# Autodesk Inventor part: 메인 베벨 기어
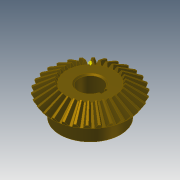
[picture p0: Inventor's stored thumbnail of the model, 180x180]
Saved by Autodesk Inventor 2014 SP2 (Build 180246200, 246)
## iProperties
Created: 2014-10
Part Number: 메인 베벨 기어
Material: Steel, Mild
Document SubType Name: Modeling
Designer: KYOUNG IL JANG
Categories: <?xml version="1.0" encoding="UTF-16"?> <MemberInstance><Categories><FamilyTemplate><FamilyTemplateParameter ValueType="xs:double" Id="1" ObjectReferenceKey="da
Mass: 269.583 g
Surface Area: 108.837 cm^2
Volume: 34.2981 cm^3
Density: 7.86 g/cm^3
Appearance: 얼룩무늬
CustomPartVersion: 1
Company: 한국ATC센터
Author: KYOUNG IL JANG
Revision Number: 1
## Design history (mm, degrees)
node "맨 위 점"
node "메쉬 평면2"
sketch "톱니 본체 스케치"
  geometry: L1 (0, 0)-(28.669, -21.997); L2 (28.669, -21.997)-(31.109, -18.336); L3 (31.109, -18.336)-(0, 0); L4 (30, -20)-(0, 0); L5 (17.219, -13.212)-(18.685, -11.013); L6 (28.669, -21.997)-(17.219, -13.212); L7 (31.109, -18.336)-(18.685, -11.013); L8 (0, -39.387)-(0, 6.564) reference; L9 (0, -20)-(31.109, -20)
  constraints: 16 end point, 4 point on line, 3 perpendicular, 2 collinear, 1 horizontal alignment, 1 vertical alignment
  dimensions: "d0" = 60 diameter of L4.start L8 (= da_de); "d1" = 57.33744 diameter of L1.end L8 (= da_dfe); "d2" = 62.2188 diameter of L2.end L8 (= da_dae); "d3" = 14.4 distance between parallel lines of L2 L5 (= da_b); "d4" = 18.3359 vertical distance of L2.end L1.start (= da_ve)
revolve "톱니 본체" sketch "톱니 본체 스케치" stored, may be unused: angle "d5" = 90 deg
node "시작점"
node "톱니 평면"
sketch "시작 스케치"
  geometry: L1 (0, -23.505)-(0, 10.645) reference; L2 (-0.709, -2.928)-(0.709, -2.928); A1 r 19.188 centre (-19.457, -7.014) between (-0.709, -2.928) and (-3.232, 3.229); A2 r 19.188 centre (19.457, -7.014) between (3.232, 3.229) and (0.709, -2.928); A3 r 57.403 centre (0, -54.083) between (3.232, 3.229) and (-3.232, 3.229); 1 further point
  constraints: 6 point on circle, 3 centre point, 3 symmetric about line, 2 end point, 1 coincident, 1 perpendicular, 1 other
  dimensions: "d7" = 19.18795 radius of A1 (= fd_rr); "d8" = 19.45712 horizontal distance of point (0, -54.083) A1.centre (= fd_x); "d9" = 47.06905 vertical distance of point (0, -54.083) A1.centre (= fd_y); "d57" = 57.40327 radius of A3 (= 0.5 x fd_dva + 0.3 x da_he); "d58" = 51.15527 distance from line of A3.centre L2 (= 0.5 x fd_dva - 1.12 x da_he)
node "끝점"
  node "끝 평면"
sketch "3D 스케치 오른쪽"
  node "Helical Curve Right" dims "d65" = 229.90621 (computed from da_dm, da_delta, da_beta), "d66" = 31.5, "d67" = 60 (= da_de), "d68" = -9.82794 (= -da_delta), "d69" = 8.10972 (computed from fd_loft, da_delta)
node "끝 평면 오른쪽"
sketch "끝 스케치 오른쪽"
  geometry: L1 (0, -41.54)-(0, 13.178) reference; L2 (-0.422, -1.69)-(0.422, -1.69); A1 r 11.427 centre (-11.587, -4.123) between (-0.422, -1.69) and (-1.925, 1.977); A2 r 11.427 centre (11.587, -4.123) between (1.925, 1.977) and (0.422, -1.69); A3 r 34.184 centre (0, -32.153) between (1.925, 1.977) and (-1.925, 1.977); 1 further point
  constraints: 6 point on circle, 3 centre point, 3 symmetric about line, 2 end point, 1 coincident, 1 perpendicular, 1 other
  dimensions: "d70" = 11.58699 horizontal distance of A3.centre A1.centre (computed from fd_x, fd_ratio); "d71" = 28.03028 vertical distance of point (0, -32.153) A1.centre (computed from fd_y, fd_ratio); "d72" = 11.4267 radius of A1 (computed from fd_rr, fd_ratio); "d73" = 30.46369 distance from line of point (0, -32.153) L2 (computed from d58, fd_ratio); "d74" = 34.18446 radius of A3 (computed from d57, fd_ratio)
feature "로프트 오른쪽" sketch "끝 스케치 오른쪽" dims "d75" = 0, "d77" = 0, "d79" = 0, "d80" = 90 deg, "d85" = 20, "d92" = 90 deg, "d93" = 90 deg, "da_teethtype" = 0 [user parameter]
sketch "3D 스케치 왼쪽"
  node "Helical Curve Left" dims "d26" = 229.90621 (computed from da_dm, da_delta, da_beta), "d27" = 8.10972 (computed from fd_loft, da_delta), "d28" = 60 (= da_de), "d29" = -9.82794 (= -da_delta)
node "끝 평면 왼쪽"
sketch "끝 스케치 왼쪽" dims "d56" = 10.3728 (derived)
  geometry: L1 (0, -43.753)-(0, 15.405) reference; L2 (-0.422, -1.678)-(0.422, -1.678); A1 r 11.427 centre (-11.587, -4.111) between (-0.422, -1.678) and (-1.925, 1.988); A2 r 11.427 centre (11.587, -4.111) between (1.925, 1.988) and (0.422, -1.678); A3 r 34.184 centre (0, -32.142) between (1.925, 1.988) and (-1.925, 1.988); 2 further points; 1 other entity
  constraints: 6 point on circle, 3 centre point, 3 symmetric about line, 2 end point, 1 coincident, 2 other
  dimensions: "d30" = 11.4267 radius of A1 (computed from fd_rr, fd_ratio); "d31" = 11.58699 horizontal distance of point (0, -32.142) A1.centre (computed from fd_x, fd_ratio); "d32" = 28.03028 vertical distance of A1.centre point (0, -32.142) (computed from fd_y, fd_ratio); "d61" = 34.18446 radius of A3 (computed from d57, fd_ratio); "d62" = 30.46369 distance from line of point (0, -32.142) L2 (computed from d58, fd_ratio)
feature "로프트 왼쪽" sketch "끝 스케치 왼쪽" dims "d35" = 0, "d37" = 0, "d39" = 0, "d40" = 90 deg, "d84" = 10, "d90" = 90 deg, "d91" = 90 deg, "da_teethtype" = 0 [user parameter]
sketch "본체 스케치"
  geometry: L1 (0, -35.038)-(0, -19.531) reference; L2 (28.669, -21.997)-(17.219, -13.212) reference; L3 (17.219, -13.212)-(0, -13.212); L4 (28.669, -21.997)-(0, -21.997)
  constraints: 4 end point, 2 perpendicular, 2 point on line
revolve "본체 고정" sketch "본체 스케치" stored, may be unused: angle "d46" = 90 deg
feature "피치 지름" dims angle "d47" = 90 deg
sketch "스케치8"
  geometry: C1 r 22.5 at (0, 0); 1 further point
  constraints: 1 centre point, 1 coincident
  dimensions: "d94" = 45 diameter of C1
extrude "돌출1" join sketch "스케치8" distance "d95" = 13; taper "d96" = 0 deg
sketch "스케치9"
  geometry: 1 further point
hole "구멍1" sketch "스케치9" at (0, 0) diameter "d97" = 17; stored, may be unused: countersink angle "d101" = 90 deg, drill point angle "d103" = 118 deg; dims "d98" = 6, "d99" = 4, "d100" = 2, "d102" = 8
sketch "스케치10"
  geometry: L1 (8.124, 2.5)-(10.8, 2.5); L2 (10.8, 2.5)-(10.8, -2.5); L3 (10.8, -2.5)-(8.124, -2.5); A1 r 8.5 centre (0, 0) between (8.124, 2.5) and (8.124, -2.5) reference; 1 further point
  constraints: 6 end point, 2 parallel, 2 point on circle, 1 horizontal, 1 perpendicular
  dimensions: "d104" = 5 distance of L1.end L2.end; "d112" = 19.3 dimension on A1 L2
extrude "돌출2" cut sketch "스케치10" stored distance "d106" = 10; taper "d107" = 0 deg
chamfer "모따기1" distance "d108" = 1; stored, may be unused: second distance "d109" = 2, angle "d110" = 45 deg
fillet "모깎기1" dims "d111" = 2
body "Solid1"
feature "로프트" dims "d17" = 0, "d18" = 90 deg, "d19" = 0, "d20" = 90 deg, "d89" = 0, "da_teethtype" = 0 [user parameter]
pattern_circular "원형 패턴" dims angle "d22" = 360 deg, "d88" = 0, "da_teethtype" = 0 [user parameter]
pattern_circular "원형 패턴 오른쪽" dims angle "d82" = 360 deg, "da_teethtype" = 0 [user parameter]
pattern_circular "원형 패턴 왼쪽" dims angle "d42" = 360 deg, "da_teethtype" = 0 [user parameter]
sketch "끝 스케치"
  geometry: L1 (0, -15.359)-(0, 6.983) reference; L2 (-0.422, -1.69)-(0.422, -1.69); A1 r 11.427 centre (-11.587, -4.123) between (-0.422, -1.69) and (-1.925, 1.977); A2 r 11.427 centre (11.587, -4.123) between (1.925, 1.977) and (0.422, -1.69); A3 r 34.184 centre (0, -32.153) between (1.925, 1.977) and (-1.925, 1.977); 1 further point
  constraints: 6 point on circle, 3 centre point, 3 symmetric about line, 2 end point, 1 coincident, 1 other
  dimensions: "d12" = 11.4267 radius of A1 (computed from fd_rr, fd_ratio); "d15" = 11.58699 horizontal distance of A1.centre point (0, -32.153) (computed from fd_x, fd_ratio); "d16" = 28.03028 vertical distance of A1.centre point (0, -32.153) (computed from fd_y, fd_ratio); "d59" = 34.18446 radius of A3 (computed from d57, fd_ratio); "d60" = 30.46369 distance from line of A3.centre L2 (computed from d58, fd_ratio)
sketch "Sketch6"
  geometry: L1 (30, -20)-(0, 0) reference; L2 (0, -37.8)-(0, 6.3) reference
body "Srf1"
other parameters: "da_b" = 14.4 [user parameter; used in 2 equation terms], "da_de" = 60 [user parameter; used in 4 equation terms], "da_dae" = 62.2188 [user parameter; used in 2 equation terms], "da_dfe" = 57.33744 [user parameter; used in 1 equation term], "da_le" = 36.05551 [user parameter; used in 1 equation term], "da_omega" = 90 deg [user parameter; used in 1 equation term], "da_beta" = 0 [user parameter; used in 2 equation terms], "da_delta" = 9.82794 [user parameter; used in 8 equation terms], "da_alpha" = 20 deg [user parameter; used in 2 equation terms], "da_he" = 4.4 [user parameter; used in 4 equation terms], "da_ve" = 18.3359 [user parameter; used in 1 equation term], "fd_dv" = 108.16654 (computed from da_de, da_delta) [user parameter; used in 1 equation term], "fd_dva" = 112.16654 (computed from da_dae, da_delta) [user parameter; used in 3 equation terms], "fd_dvb" = 101.6433 (computed from fd_dv, da_alpha) [user parameter; used in 2 equation terms], "da_zv" = 540.83269 [user parameter; used in 1 equation term], "fd_loft" = 14.62 (= da_b + 0.05 x da_he) [user parameter; used in 4 equation terms], "fd_ratio" = 5.95514 (computed from da_le, fd_loft) [user parameter; used in 15 equation terms], "fd_rr" = 19.18795 (computed from fd_dd, fd_dvb) [user parameter; used in 6 equation terms], "fd_angle" = 0.29367 (computed from da_zv) [user parameter; used in 4 equation terms], "fd_x1" = 1.58802 (computed from da_dvw, fd_angle) [user parameter; used in 1 equation term], "fd_y1" = 54.05995 (computed from da_dvw, fd_angle) [user parameter; used in 1 equation term], "fd_x2" = 17.8691 (computed from fd_rr, fd_angle2, fd_angle) [user parameter; used in 1 equation term], "fd_y2" = 6.9909 (computed from fd_rr, fd_angle2, fd_angle) [user parameter; used in 1 equation term], "fd_x" = 19.45712 (= fd_x1 + fd_x2) [user parameter; used in 4 equation terms], "fd_y" = 47.06905 (= fd_y1 - fd_y2) [user parameter; used in 4 equation terms], "fd_angle2" = 3.43555 (computed from fd_dvb, fd_dd, da_alpha) [user parameter; used in 2 equation terms], "fd_dd" = 108.64654 (= fd_dva - 0.8 x da_he) [user parameter; used in 2 equation terms], "da_dvw" = 108.16654 [user parameter; used in 2 equation terms], "d11" = 14.62 (= fd_loft), "da_dm" = 48.01848 [user parameter; used in 2 equation terms], "da_x" = 0 [user parameter], "da_m" = 2 [user parameter], "d48" = 0, "d49" = 0, "d50" = 90 deg (= da_omega), "d51" = 6 deg (computed from da_z), "d52" = 0, "d53" = 0, "d54" = 0
